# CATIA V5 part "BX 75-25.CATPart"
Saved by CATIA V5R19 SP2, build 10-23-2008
Part number: BX 75-25
Bounding box of the stored display mesh (mm): x -15.868 to 15.868, y -15.868 to 15.868, z 0 to 120
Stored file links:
  C:\Users\Bora\Desktop\3D Katı model\BX serisi\BX 75\BX 75-25.CATPart
  C:\Program Files\Dassault Systemes\B19\intel_a\reffiles\standard\MetricThickPitch.txt
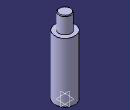
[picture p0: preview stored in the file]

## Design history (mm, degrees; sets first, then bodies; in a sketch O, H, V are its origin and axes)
Body1 (main body)
  Sketch1 on yz-plane, origin (0, 0, 0), H (0, 1, 0), V (0, 0, 1)
    line L1 (16, 94) -> (16, 0)
    point P4 (9.5, 119)
    line L2 (9.5, 119) -> (9.5, 94)
    point P6 (9.5, 119)
    arc A1 centre (8.5, 119) radius 1 from (9.5, 119) to (8.5, 120) ccw
    line L3 (8.5, 120) -> (0, 120)
    point P7 (0, 120)
    line L4 (9.5, 94) -> (16, 94)
    line L5 (16, 0) -> (0, 0)
    tangency: L3 A1
    coincidence: P7 V, P4 P6
    horizontal: L4 H, L5 H
  Shaft1: profile Sketch1, axis Sketch1.V, angle 360
  Sketch2 on face of Shaft1 from Sketch1.L5, origin (0, 0, 0), H (1, 0, 0), V (0, -1, 0)
    point P1 (7.5, 0)
    distance V P1 = 7.5
  Hole1: placed by Sketch2, at (7.5, 0, 0) direction (0, 0, 1), diameter 3.242, depth 5, threaded "M4", thread diameter 4, thread depth 5, pitch 0.7
  Sketch3 on face of Shaft1 from Sketch1.L5, origin (0, 0, 0), H (1, 0, 0), V (0, -1, 0)
    point P1 (-7.5, 0)
    distance P1 V = 7.5
  Hole2: placed by Sketch3, at (-7.5, 0, 0) direction (0, 0, 1), diameter 3.242, depth 5, threaded "M4", thread diameter 4, thread depth 5, pitch 0.7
